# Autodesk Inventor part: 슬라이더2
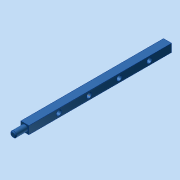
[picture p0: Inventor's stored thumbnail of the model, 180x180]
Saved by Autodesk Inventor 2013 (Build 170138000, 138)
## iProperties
Company: 한국ATC센터
Created: 2015-04
Part Number: 슬라이더2
Document SubType Name: Modeling
Designer: KYOUNG IL JANG
Density: 1 g/cm^3
Material: 강철
Mass: 8.7906 g
Surface Area: 52.3143 cm^2
Volume: 8.7906 cm^3
Author: KYOUNG IL JANG
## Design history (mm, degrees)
sketch "스케치3"
  geometry: L1 (4, 142)-(-4, 142); L2 (-4, 142)-(-4, 0); L3 (-4, 0)-(4, 0); L4 (4, 0)-(4, 142); 3 further points
  constraints: 8 end point, 2 coincident, 2 parallel, 1 horizontal, 1 midpoint, 1 perpendicular
  dimensions: "d5" = 8 distance of L1.start L1.end; "d6" = 142 distance of L1.end L2.end
extrude "돌출3" new body sketch "스케치3" stored distance "d7" = 8; taper "d8" = 0 deg
sketch "스케치4"
  geometry: L1 (8, 0)-(0, 0) reference; 3 further points
  constraints: 1 midpoint, 1 vertical alignment
  dimensions: "d9" = 30 distance of point (4, 30) point (4, 0)
hole "구멍1" sketch "스케치4" at (4, 30) diameter "d10" = 5; stored, may be unused: countersink angle "d14" = 90 deg, drill point angle "d16" = 118 deg; dims "d11" = 6, "d12" = 4, "d13" = 2, "d15" = 8
sketch "스케치5"
  geometry: C1 r 3 at (4, -4); 1 further point
  constraints: 1 centre point, 1 coincident
  dimensions: "d20" = 6 diameter of C1
extrude "돌출4" join sketch "스케치5" distance "d21" = 12; taper "d22" = 0 deg
chamfer "모따기1" distance "d23" = 1; stored, may be unused: second distance "d24" = 2, angle "d25" = 45 deg
node "작업 평면2"
  node "작업축1"
node "솔리드1"
pattern_linear "직사각형 패턴1" dims "d19" = 30
node "솔리드2"
other parameters: "d26" = 0
